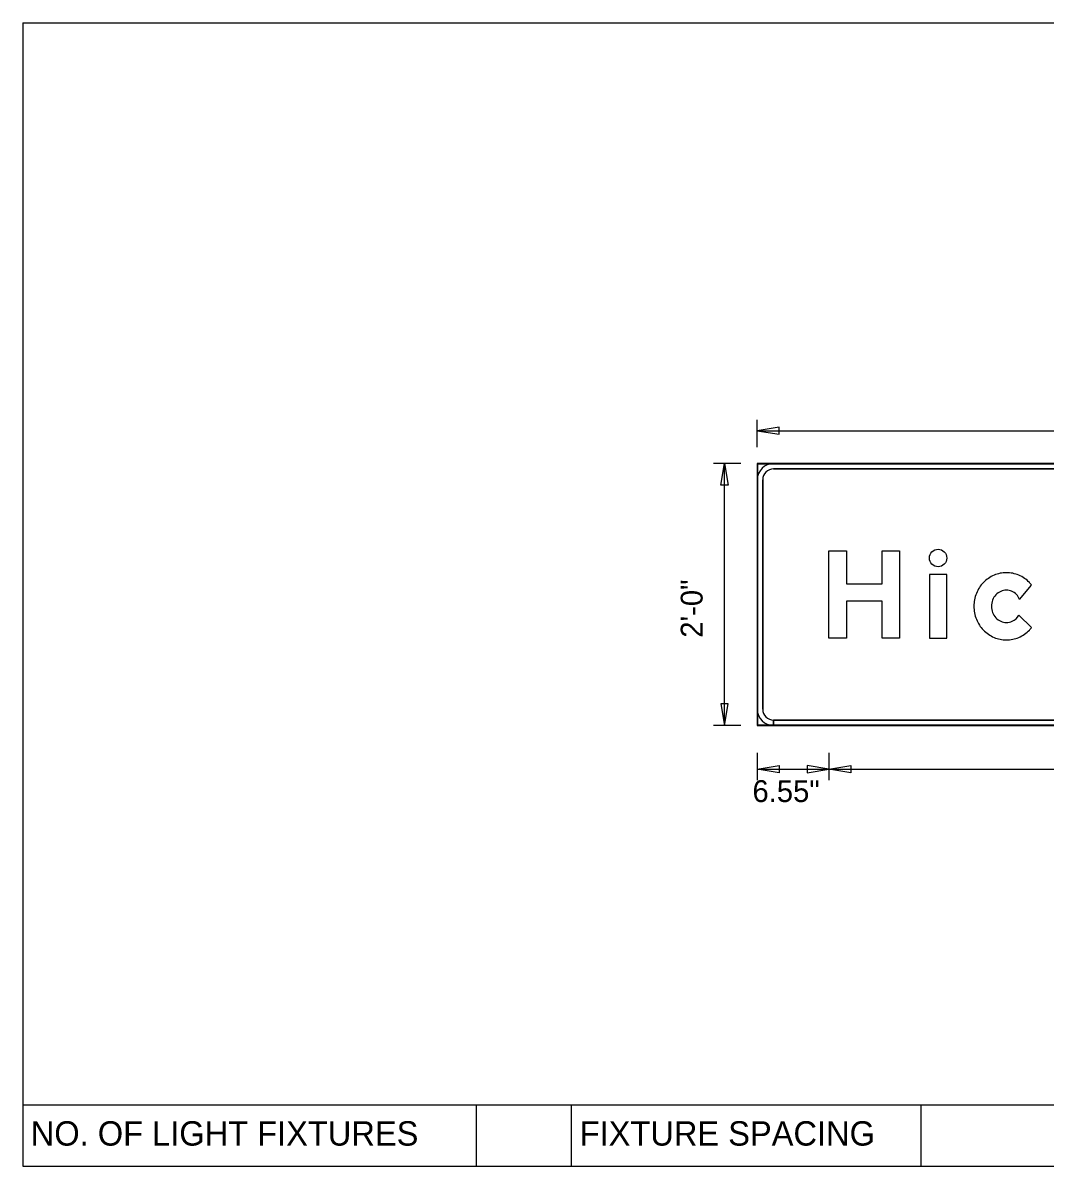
# Model space of a CAD drawing. Extents: x 1374 to 1480, y 568 to 638.
# Drawn here: x 1410.26 to 1418.05, y 578.92 to 587.64 of the extents above; entities that cross this region are included whole.
import ezdxf

# ---------------------------------------------------------------- set-up
doc = ezdxf.new("R2010")
doc.units = 0
for name, color, linetype in [('GSBWFill', 7, 'Continuous'), ('GSColorFill', 7, 'Continuous'), ('GSDims', 7, 'Continuous'), ('GSOutline', 7, 'Continuous'), ('SheetLinesMisc2_dp', 7, 'Continuous'), ('TextMinor', 7, 'Continuous')]:
    doc.layers.add(name, color=color, linetype=linetype)

msp = doc.modelspace()

# ---------------------------------------------------------------- linework, layer by layer
at = {"layer": 'GSBWFill'}
for p, q in [((1422.8581, 584.2826), (1415.8581, 584.2826)), ((1415.8581, 584.2826), (1415.8581, 582.2826)), ((1422.7331, 584.2826), (1415.9831, 584.2826)), ((1415.9831, 584.2409), (1422.7331, 584.2409)), ((1415.8581, 584.1576), (1415.8581, 582.4076)), ((1415.8997, 582.4076), (1415.8997, 584.1576)), ((1417.8588, 583.2433), (1417.9514, 583.355)), ((1417.9514, 583.0301), (1417.8542, 583.1252)), ((1415.8581, 582.2826), (1422.8581, 582.2826)), ((1415.9831, 582.2826), (1415.9831, 582.3242)), ((1422.7331, 582.3242), (1415.9835, 582.3242)), ((1415.9835, 582.3242), (1415.9835, 582.2826)), ((1415.9835, 582.2826), (1422.7331, 582.2826))]:
    msp.add_line(p, q, dxfattribs=at)
for points in [[(1416.9447, 582.9492), (1416.8114, 582.9492), (1416.8114, 583.232), (1416.5381, 583.232), (1416.5381, 582.9492), (1416.4047, 582.9492), (1416.4047, 583.6159), (1416.5381, 583.6159), (1416.5381, 583.3653), (1416.8114, 583.3653), (1416.8114, 583.6159), (1416.9447, 583.6159)], [(1417.1714, 582.9492), (1417.3047, 582.9492), (1417.3047, 583.4359), (1417.1714, 583.4359)]]:
    msp.add_lwpolyline(points, close=True, dxfattribs=at)
for centre, radius, start, end in [((1415.9831, 584.1576), 0.125, 90, 180), ((1415.9831, 584.1576), 0.0833, 90, 180), ((1415.9831, 582.4076), 0.125, 180, 270), ((1415.9831, 582.4076), 0.0833, 180, 270)]:
    msp.add_arc(centre, radius, start, end, dxfattribs=at)
msp.add_ellipse((1417.2381, 583.5609), major_axis=(0, 0.0667), ratio=0.999988, dxfattribs=at)
for centre, major_axis, start_param, end_param in [((1417.7683, 583.196), (0, 0.2563), 0.80258, 1.190101), ((1417.7629, 583.2012), (0, 0.2487), 0.404999, 0.80258), ((1417.7594, 583.2094), (0, 0.2398), 0, 0.404999), ((1417.7594, 583.2094), (0, 0.2398), 5.878187, 6.283185), ((1417.7559, 583.2012), (0, 0.2487), 5.480605, 5.878187), ((1417.7504, 583.196), (0, 0.2563), 5.381938, 5.480605), ((1417.7768, 583.1926), (0, 0.2655), 1.190101, 1.570796), ((1417.763, 583.2011), (0, 0.1156), 0.419139, 0.821819), ((1417.7594, 583.2091), (0, 0.1068), 0, 0.419139), ((1417.7594, 583.2091), (0, 0.1068), 5.902947, 6.283185), ((1417.7622, 583.2144), (0, 0.1009), 5.002891, 5.909172), ((1417.7772, 583.1926), (0, 0.1325), 1.20321, 1.570796), ((1417.7685, 583.1959), (0, 0.1232), 0.821819, 1.20321), ((1417.7768, 583.1926), (0, 0.2655), 1.570796, 1.951491), ((1417.7772, 583.1926), (0, 0.1325), 1.570796, 1.938383), ((1417.7685, 583.1892), (0, 0.1232), 1.938383, 2.319773), ((1417.7734, 583.1624), (0, 0.089), 3.479501, 4.280948), ((1417.7683, 583.1892), (0, 0.2563), 1.951491, 2.339013), ((1417.763, 583.1841), (0, 0.1156), 2.319773, 2.722453), ((1417.7594, 583.176), (0, 0.1068), 2.722453, 3.141593), ((1417.7594, 583.176), (0, 0.1068), 3.141593, 3.560732), ((1417.7504, 583.1892), (0, 0.2563), 3.944173, 4.04284), ((1417.7629, 583.1839), (0, 0.2487), 2.339013, 2.736594), ((1417.7594, 583.1757), (0, 0.2398), 2.736594, 3.141593), ((1417.7594, 583.1757), (0, 0.2398), 3.141593, 3.546591), ((1417.7559, 583.1839), (0, 0.2487), 3.546591, 3.944173)]:
    msp.add_ellipse(centre, major_axis=major_axis, ratio=0.999996, start_param=start_param, end_param=end_param, dxfattribs=at)
at = {"layer": 'GSColorFill'}
for p, q in [((1422.8581, 584.2826), (1415.8581, 584.2826)), ((1415.8581, 584.2826), (1415.8581, 582.2826)), ((1422.8581, 584.2826), (1415.8581, 584.2826)), ((1415.8581, 584.2826), (1415.8581, 582.2868)), ((1415.8622, 582.2868), (1415.8622, 584.2784)), ((1415.8622, 584.2784), (1422.8539, 584.2784)), ((1422.7331, 584.2826), (1415.9831, 584.2826)), ((1415.9831, 584.2409), (1422.7331, 584.2409)), ((1415.8581, 584.1576), (1415.8581, 582.4076)), ((1415.8997, 582.4076), (1415.8997, 584.1576)), ((1417.8588, 583.2433), (1417.9514, 583.355)), ((1417.9514, 583.0301), (1417.8542, 583.1252)), ((1415.8581, 582.2868), (1415.8622, 582.2868)), ((1422.8539, 582.2867), (1415.8581, 582.2867)), ((1415.8581, 582.2867), (1415.8581, 582.2826)), ((1415.8581, 582.2826), (1422.8581, 582.2826)), ((1415.8581, 582.2826), (1422.8581, 582.2826)), ((1415.9831, 582.2826), (1415.9831, 582.3242)), ((1422.7331, 582.3242), (1415.9835, 582.3242)), ((1415.9835, 582.3242), (1415.9835, 582.2826)), ((1415.9835, 582.2826), (1422.7331, 582.2826))]:
    msp.add_line(p, q, dxfattribs=at)
for points in [[(1416.9447, 582.9492), (1416.8114, 582.9492), (1416.8114, 583.232), (1416.5381, 583.232), (1416.5381, 582.9492), (1416.4047, 582.9492), (1416.4047, 583.6159), (1416.5381, 583.6159), (1416.5381, 583.3653), (1416.8114, 583.3653), (1416.8114, 583.6159), (1416.9447, 583.6159)], [(1417.1714, 582.9492), (1417.3047, 582.9492), (1417.3047, 583.4359), (1417.1714, 583.4359)]]:
    msp.add_lwpolyline(points, close=True, dxfattribs=at)
for centre, radius, start, end in [((1415.9831, 584.1576), 0.125, 90, 180), ((1415.9831, 584.1576), 0.0833, 90, 180), ((1415.9831, 582.4076), 0.125, 180, 270), ((1415.9831, 582.4076), 0.0833, 180, 270)]:
    msp.add_arc(centre, radius, start, end, dxfattribs=at)
msp.add_ellipse((1417.2381, 583.5609), major_axis=(0, 0.0667), ratio=0.999988, dxfattribs=at)
for centre, major_axis, start_param, end_param in [((1417.7683, 583.196), (0, 0.2563), 0.80258, 1.190101), ((1417.7629, 583.2012), (0, 0.2487), 0.404999, 0.80258), ((1417.7594, 583.2094), (0, 0.2398), 0, 0.404999), ((1417.7594, 583.2094), (0, 0.2398), 5.878187, 6.283185), ((1417.7559, 583.2012), (0, 0.2487), 5.480605, 5.878187), ((1417.7504, 583.196), (0, 0.2563), 5.381938, 5.480605), ((1417.7768, 583.1926), (0, 0.2655), 1.190101, 1.570796), ((1417.763, 583.2011), (0, 0.1156), 0.419139, 0.821819), ((1417.7594, 583.2091), (0, 0.1068), 0, 0.419139), ((1417.7594, 583.2091), (0, 0.1068), 5.902947, 6.283185), ((1417.7622, 583.2144), (0, 0.1009), 5.002891, 5.909172), ((1417.7772, 583.1926), (0, 0.1325), 1.20321, 1.570796), ((1417.7685, 583.1959), (0, 0.1232), 0.821819, 1.20321), ((1417.7768, 583.1926), (0, 0.2655), 1.570796, 1.951491), ((1417.7772, 583.1926), (0, 0.1325), 1.570796, 1.938383), ((1417.7685, 583.1892), (0, 0.1232), 1.938383, 2.319773), ((1417.7734, 583.1624), (0, 0.089), 3.479501, 4.280948), ((1417.7683, 583.1892), (0, 0.2563), 1.951491, 2.339013), ((1417.763, 583.1841), (0, 0.1156), 2.319773, 2.722453), ((1417.7594, 583.176), (0, 0.1068), 2.722453, 3.141593), ((1417.7594, 583.176), (0, 0.1068), 3.141593, 3.560732), ((1417.7504, 583.1892), (0, 0.2563), 3.944173, 4.04284), ((1417.7629, 583.1839), (0, 0.2487), 2.339013, 2.736594), ((1417.7594, 583.1757), (0, 0.2398), 2.736594, 3.141593), ((1417.7594, 583.1757), (0, 0.2398), 3.141593, 3.546591), ((1417.7559, 583.1839), (0, 0.2487), 3.546591, 3.944173)]:
    msp.add_ellipse(centre, major_axis=major_axis, ratio=0.999996, start_param=start_param, end_param=end_param, dxfattribs=at)
at = {"layer": 'GSDims'}
for p, q in [((1415.8581, 584.4076), (1415.8581, 584.6159)), ((1415.8581, 584.5326), (1422.8581, 584.5326)), ((1415.8581, 584.4076), (1415.8581, 584.4076)), ((1415.7331, 584.2826), (1415.5247, 584.2826)), ((1415.6081, 582.2826), (1415.6081, 584.2826)), ((1415.7331, 584.2826), (1415.7331, 584.2826)), ((1415.7331, 582.2826), (1415.5247, 582.2826)), ((1415.7331, 582.2826), (1415.7331, 582.2826)), ((1415.8581, 582.0742), (1415.8581, 581.8659)), ((1415.8581, 582.0742), (1415.8581, 581.8659)), ((1416.4047, 582.0742), (1416.4047, 581.8659)), ((1416.4047, 582.0742), (1416.4047, 581.8659)), ((1415.8581, 581.9492), (1416.4047, 581.9492)), ((1416.4047, 581.9492), (1422.3114, 581.9492))]:
    msp.add_line(p, q, dxfattribs=at)
for points in [[(1415.8581, 584.5326), (1416.0247, 584.5048), (1416.0247, 584.5603)], [(1415.6081, 584.2826), (1415.6358, 584.1159), (1415.5803, 584.1159)], [(1415.6081, 582.2826), (1415.6358, 582.4492), (1415.5803, 582.4492)], [(1415.8581, 581.9492), (1416.0247, 581.977), (1416.0247, 581.9215)], [(1416.4047, 581.9492), (1416.2381, 581.977), (1416.2381, 581.9215)], [(1416.4047, 581.9492), (1416.5714, 581.977), (1416.5714, 581.9215)]]:
    msp.add_lwpolyline(points, close=True, dxfattribs=at)
at = {"layer": 'GSOutline'}
for p, q in [((1422.8581, 584.2826), (1415.8581, 584.2826)), ((1415.8581, 584.2826), (1415.8581, 582.2826)), ((1422.7331, 584.2826), (1415.9831, 584.2826)), ((1422.7331, 584.2409), (1415.9831, 584.2409)), ((1415.8581, 584.1576), (1415.8581, 582.4076)), ((1415.8997, 584.1576), (1415.8997, 582.4076)), ((1417.8588, 583.2433), (1417.9514, 583.355)), ((1417.9514, 583.0301), (1417.8542, 583.1252)), ((1415.8581, 582.2826), (1422.8581, 582.2826)), ((1415.9831, 582.3242), (1422.7331, 582.3242)), ((1415.9831, 582.2826), (1422.7331, 582.2826))]:
    msp.add_line(p, q, dxfattribs=at)
for points in [[(1416.9447, 582.9492), (1416.8114, 582.9492), (1416.8114, 583.232), (1416.5381, 583.232), (1416.5381, 582.9492), (1416.4047, 582.9492), (1416.4047, 583.6159), (1416.5381, 583.6159), (1416.5381, 583.3653), (1416.8114, 583.3653), (1416.8114, 583.6159), (1416.9447, 583.6159)], [(1417.1714, 582.9492), (1417.3047, 582.9492), (1417.3047, 583.4359), (1417.1714, 583.4359)]]:
    msp.add_lwpolyline(points, close=True, dxfattribs=at)
for centre, radius, start, end in [((1415.9831, 584.1576), 0.125, 90, 180), ((1415.9831, 584.1576), 0.0833, 90, 180), ((1415.9831, 582.4076), 0.125, 180, 270), ((1415.9831, 582.4076), 0.0833, 180, 270)]:
    msp.add_arc(centre, radius, start, end, dxfattribs=at)
msp.add_ellipse((1417.2381, 583.5609), major_axis=(0, 0.0667), ratio=0.999988, dxfattribs=at)
for centre, major_axis, start_param, end_param in [((1417.7683, 583.196), (0, 0.2563), 0.80258, 1.190101), ((1417.7629, 583.2012), (0, 0.2487), 0.404999, 0.80258), ((1417.7594, 583.2094), (0, 0.2398), 0, 0.404999), ((1417.7594, 583.2094), (0, 0.2398), 5.878187, 6.283185), ((1417.7559, 583.2012), (0, 0.2487), 5.480605, 5.878187), ((1417.7504, 583.196), (0, 0.2563), 5.381938, 5.480605), ((1417.7768, 583.1926), (0, 0.2655), 1.190101, 1.570796), ((1417.763, 583.2011), (0, 0.1156), 0.419139, 0.821819), ((1417.7594, 583.2091), (0, 0.1068), 0, 0.419139), ((1417.7594, 583.2091), (0, 0.1068), 5.902947, 6.283185), ((1417.7622, 583.2144), (0, 0.1009), 5.002891, 5.909172), ((1417.7772, 583.1926), (0, 0.1325), 1.20321, 1.570796), ((1417.7685, 583.1959), (0, 0.1232), 0.821819, 1.20321), ((1417.7768, 583.1926), (0, 0.2655), 1.570796, 1.951491), ((1417.7772, 583.1926), (0, 0.1325), 1.570796, 1.938383), ((1417.7685, 583.1892), (0, 0.1232), 1.938383, 2.319773), ((1417.7734, 583.1624), (0, 0.089), 3.479501, 4.280948), ((1417.7683, 583.1892), (0, 0.2563), 1.951491, 2.339013), ((1417.763, 583.1841), (0, 0.1156), 2.319773, 2.722453), ((1417.7594, 583.176), (0, 0.1068), 2.722453, 3.141593), ((1417.7594, 583.176), (0, 0.1068), 3.141593, 3.560732), ((1417.7504, 583.1892), (0, 0.2563), 3.944173, 4.04284), ((1417.7629, 583.1839), (0, 0.2487), 2.339013, 2.736594), ((1417.7594, 583.1757), (0, 0.2398), 2.736594, 3.141593), ((1417.7594, 583.1757), (0, 0.2398), 3.141593, 3.546591), ((1417.7559, 583.1839), (0, 0.2487), 3.546591, 3.944173)]:
    msp.add_ellipse(centre, major_axis=major_axis, ratio=0.999996, start_param=start_param, end_param=end_param, dxfattribs=at)
at = {"layer": 'SheetLinesMisc2_dp'}
for p, q in [((1410.2555, 587.644), (1428.1633, 587.644)), ((1410.2555, 587.644), (1410.2555, 578.9337)), ((1410.2556, 579.3887), (1428.1633, 579.3887)), ((1413.7145, 579.3887), (1413.7145, 578.9214)), ((1414.4393, 579.3887), (1414.4393, 578.9214)), ((1417.1058, 579.3887), (1417.1058, 578.9214)), ((1410.2555, 578.9337), (1410.2555, 578.9219)), ((1410.2556, 578.9214), (1428.1633, 578.9214))]:
    msp.add_line(p, q, dxfattribs=at)

# ---------------------------------------------------------------- texts
at = {"layer": 'GSDims'}
msp.add_text('2\'-0"', height=0.16667, rotation=90, dxfattribs=at).set_placement((1415.4414, 582.9532))
msp.add_text('6.55"', height=0.16667, dxfattribs=at).set_placement((1415.8219, 581.6992))
at = {"layer": 'TextMinor'}
for s, p in [('NO. OF LIGHT FIXTURES', (1410.3157, 579.0779)), ('FIXTURE SPACING', (1414.5037, 579.0779))]:
    msp.add_text(s, height=0.186009, dxfattribs=at).set_placement(p)

doc.saveas('drawing.dxf')
